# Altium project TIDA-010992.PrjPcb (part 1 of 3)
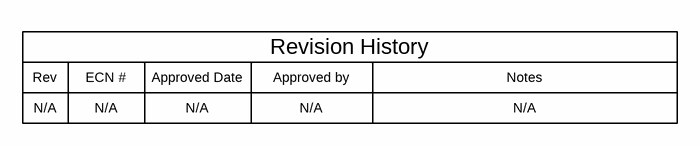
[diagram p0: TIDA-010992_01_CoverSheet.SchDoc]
CopyrightYear: 2025; DrawnBy: Chen Gao; PCB_Layout: Chen Gao; PCB_Rev: E1; PRJ_Customer: Public Release; PRJ_Engineer: Chen Gao; PRJ_Number: TIDA-010992; PRJ_Title: TIDA-010992; SCH_Rev: E1; TechSupport: http://www.ti.com/support; TID: TIDA-010992
13 sheets, 522 parts. Net scope: global (net labels, ports and power ports of the same name join across sheets).
Board file: TIDA-010992.PcbDoc
Sheets:
  TIDA-010992_01_CoverSheet.SchDoc
  TIDA-010992_02_Power.SchDoc
  TIDA-010992_03_IO_Map_Debug.SchDoc
  TIDA-010992_04_BOOT_SoC power_CLK.SchDoc
  TIDA-010992_05_ETH_Conn.SchDoc
  TIDA-010992_06_DRV_AXIS1.SchDoc
  TIDA-010992_07_DRV_AXIS2.SchDoc
  TIDA-010992_08_DRV_AXIS3.SchDoc
  TIDA-010992_09_DRV_AXIS4.SchDoc
  TIDA-010992_10_DRV_AXIS5.SchDoc
  TIDA-010992_11_DRV_AXIS6.SchDoc
  TIDA-010992_12_Connectors.SchDoc
  TIDA-010992_Hardware.SchDoc

## Sheet TIDA-010992_01_CoverSheet.SchDoc
size 431 x 279 mm; Date: Not shown in title block; ApprovedBy: Not shown in title block; CheckedBy: Not shown in title block; Author: Not shown in title block; CompanyName: Not shown in title block; Engineer: Not shown in title block; Organization: Not shown in title block; Address1: Not shown in title block; Address2: Not shown in title block; Address3: Not shown in title block; Address4: Not shown in title block; DocumentNumber: 1; Revision: Use project parameter SCH_Rev; SheetNumber: 1; SheetTotal: 13; PageSetup: Record=PageOptions¦CenterHorizontal=True¦CenterVertical=True¦PrintScale=1.00¦XCorrection=1.00¦YCorrection=1.00¦PrintKind=0¦BorderSize=5000000¦LeftOffset=0¦BottomOffset=0¦Orientation=2¦PaperLength=1000¦PaperWidth=1000¦Scale=100¦PaperSource=15¦PrintQuality=600¦MediaType=1¦DitherType=10¦PaperKind=Letter¦PrintScaleMode=1

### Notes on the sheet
- Rev
- N/A
- ECN #
- Approved Date
- Approved by
- Revision History
- Notes

## Sheet TIDA-010992_02_Power.SchDoc
size 431 x 279 mm; Date: Not shown in title block; ApprovedBy: Not shown in title block; CheckedBy: Not shown in title block; Author: Not shown in title block; CompanyName: Not shown in title block; Engineer: Not shown in title block; Organization: Not shown in title block; Address1: Not shown in title block; Address2: Not shown in title block; Address3: Not shown in title block; Address4: Not shown in title block; DocumentNumber: 2; Revision: Use project parameter SCH_Rev; SheetNumber: 2; SheetTotal: 13; PageSetup: Record=PageOptions¦CenterHorizontal=True¦CenterVertical=True¦PrintScale=1.00¦XCorrection=1.00¦YCorrection=1.00¦PrintKind=0¦BorderSize=5000000¦LeftOffset=0¦BottomOffset=0¦Orientation=2¦PaperLength=1000¦PaperWidth=1000¦Scale=100¦PaperSource=15¦PrintQuality=600¦MediaType=1¦DitherType=10¦PaperKind=Letter¦PrintScaleMode=1
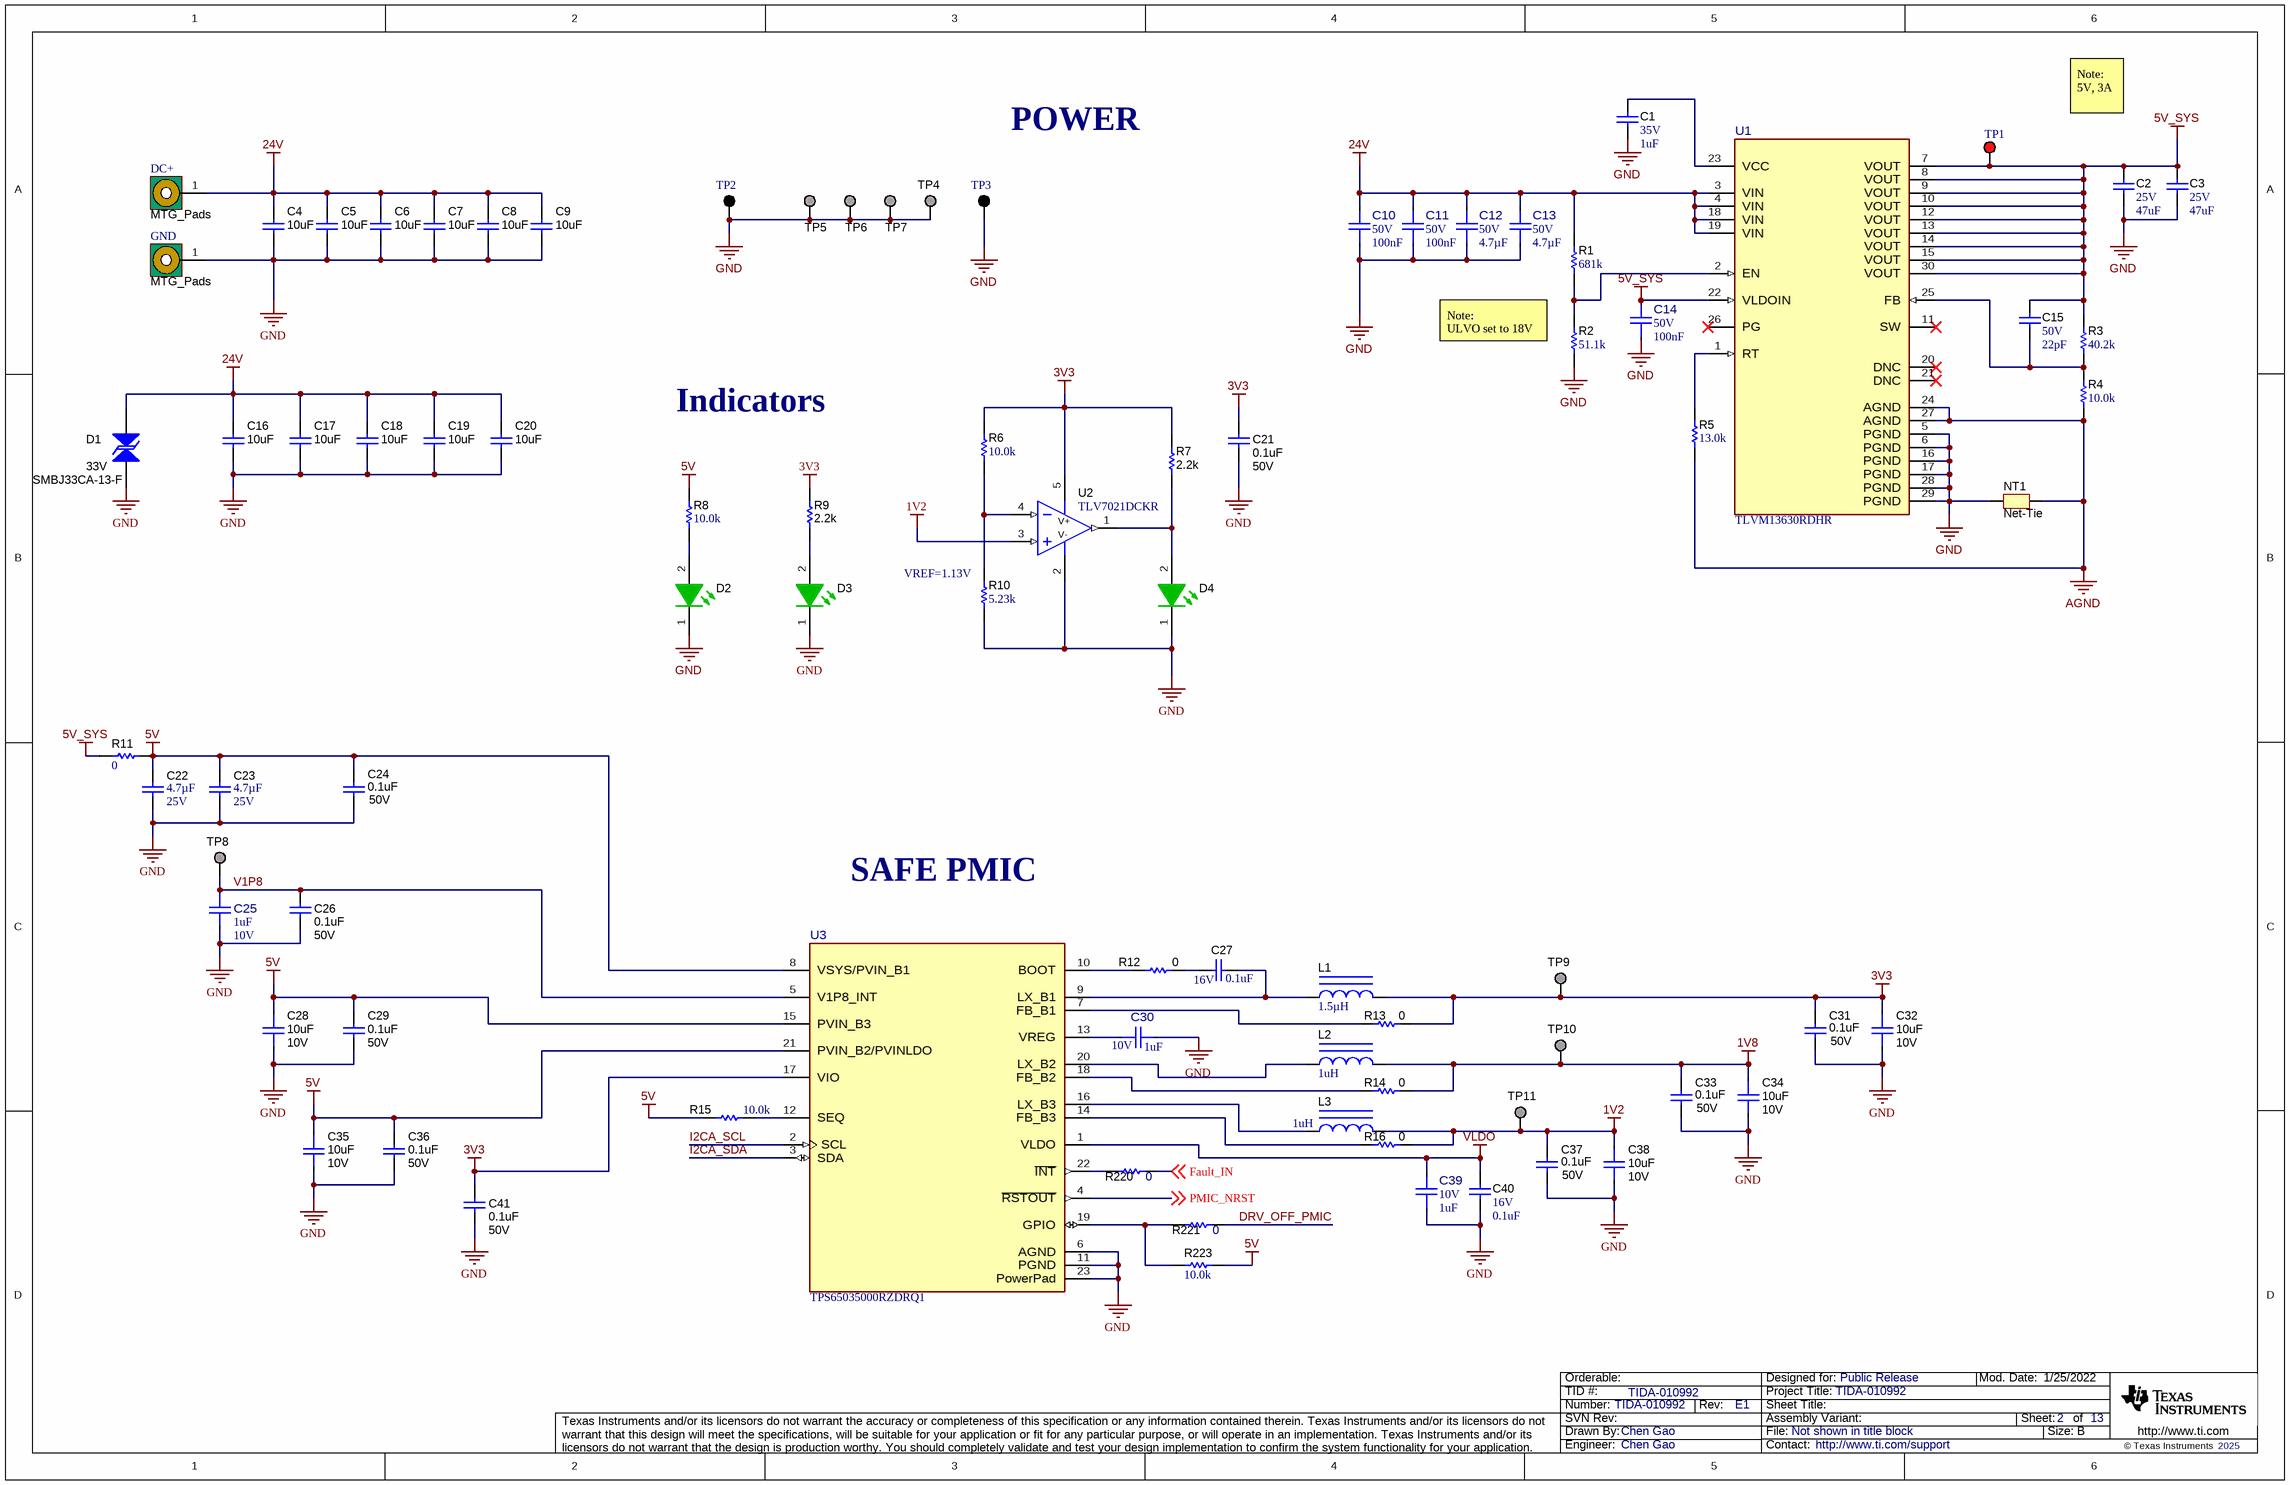
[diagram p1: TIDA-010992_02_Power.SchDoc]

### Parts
C1  VDC_V: 35V  ValueDisplayed: 1uF  [0402L]  (hidden comment: GRM155R6YA105ME11D)
C2  VDC_V: 25V  ValueDisplayed: 47uF  [1206_190]  (hidden comment: C3216X5R1E476M160AC)
C3  VDC_V: 25V  ValueDisplayed: 47uF  [1206_190]  (hidden comment: C3216X5R1E476M160AC)
C4  ValueDisplayed: 10uF  [1210_270L]  (hidden comment: GRM32ER71H106KA12L)
C5  ValueDisplayed: 10uF  [1210_270L]  (hidden comment: GRM32ER71H106KA12L)
C6  ValueDisplayed: 10uF  [1210_270L]  (hidden comment: GRM32ER71H106KA12L)
C7  ValueDisplayed: 10uF  [1210_270L]  (hidden comment: GRM32ER71H106KA12L)
C8  ValueDisplayed: 10uF  [1210_270L]  (hidden comment: GRM32ER71H106KA12L)
C9  ValueDisplayed: 10uF  [1210_270L]  (hidden comment: GRM32ER71H106KA12L)
C10  VDC_V: 50V  ValueDisplayed: 100nF  [FP-885012205086_0402-MFG]  (hidden comment: 885012205086)
C11  VDC_V: 50V  ValueDisplayed: 100nF  [FP-885012205086_0402-MFG]  (hidden comment: 885012205086)
C12  VDC_V: 50V  Cap_F: 4.7µF  [FP-C2012X7R1H475K125AC_0805-MFG]  (hidden comment: C2012X7R1H475K125AC)
C13  VDC_V: 50V  Cap_F: 4.7µF  [FP-C2012X7R1H475K125AC_0805-MFG]  (hidden comment: C2012X7R1H475K125AC)
C14  VDC_V: 50V  ValueDisplayed: 100nF  [FP-885012205086_0402-MFG]  (hidden comment: 885012205086)
C15  VDC_V: 50V  ValueDisplayed: 22pF  [0402L]  (hidden comment: CGA2B2C0G1H220J050BA)
C16  ValueDisplayed: 10uF  [1210_270L]  (hidden comment: GRM32ER71H106KA12L)
C17  ValueDisplayed: 10uF  [1210_270L]  (hidden comment: GRM32ER71H106KA12L)
C18  ValueDisplayed: 10uF  [1210_270L]  (hidden comment: GRM32ER71H106KA12L)
C19  ValueDisplayed: 10uF  [1210_270L]  (hidden comment: GRM32ER71H106KA12L)
C20  ValueDisplayed: 10uF  [1210_270L]  (hidden comment: GRM32ER71H106KA12L)
C21  VDC_V: 50V  ValueDisplayed: 0.1uF  [0402]  (hidden comment: CGA2B3X7R1H104M050BB)
C22  VDC_V: 25V  ValueDisplayed: 4.7µF  [0805L]  (hidden comment: CGA4J1X7R1E475K125AC)
C23  VDC_V: 25V  ValueDisplayed: 4.7µF  [0805L]  (hidden comment: CGA4J1X7R1E475K125AC)
C24  VDC_V: 50V  ValueDisplayed: 0.1uF  [0402]  (hidden comment: CGA2B3X7R1H104M050BB)
C25  VDC_V: 10V  ValueDisplayed: 1uF  [FP-GRM155C71A105KE11D_0402-MFG]  (hidden comment: GRM155C71A105KE11D)
C26  VDC_V: 50V  ValueDisplayed: 0.1uF  [0402]  (hidden comment: CGA2B3X7R1H104M050BB)
C27  VDC_V: 16V  ValueDisplayed: 0.1uF  [0201]  (hidden comment: GRM033Z71C104KE14D)
C28  VDC_V: 10V  ValueDisplayed: 10uF  [FP-CGA4J3X7S1A106K125AE_0805-MFG]  (hidden comment: CGA4J3X7S1A106K125AE)
C29  VDC_V: 50V  ValueDisplayed: 0.1uF  [0402]  (hidden comment: CGA2B3X7R1H104M050BB)
C30  VDC_V: 10V  ValueDisplayed: 1uF  [FP-GRM155C71A105KE11D_0402-MFG]  (hidden comment: GRM155C71A105KE11D)
C31  VDC_V: 50V  ValueDisplayed: 0.1uF  [0402]  (hidden comment: CGA2B3X7R1H104M050BB)
C32  VDC_V: 10V  ValueDisplayed: 10uF  [FP-CGA4J3X7S1A106K125AE_0805-MFG]  (hidden comment: CGA4J3X7S1A106K125AE)
C33  VDC_V: 50V  ValueDisplayed: 0.1uF  [0402]  (hidden comment: CGA2B3X7R1H104M050BB)
C34  VDC_V: 10V  ValueDisplayed: 10uF  [FP-CGA4J3X7S1A106K125AE_0805-MFG]  (hidden comment: CGA4J3X7S1A106K125AE)
C35  VDC_V: 10V  ValueDisplayed: 10uF  [FP-CGA4J3X7S1A106K125AE_0805-MFG]  (hidden comment: CGA4J3X7S1A106K125AE)
C36  VDC_V: 50V  ValueDisplayed: 0.1uF  [0402]  (hidden comment: CGA2B3X7R1H104M050BB)
C37  VDC_V: 50V  ValueDisplayed: 0.1uF  [0402]  (hidden comment: CGA2B3X7R1H104M050BB)
C38  VDC_V: 10V  ValueDisplayed: 10uF  [FP-CGA4J3X7S1A106K125AE_0805-MFG]  (hidden comment: CGA4J3X7S1A106K125AE)
C39  VDC_V: 10V  ValueDisplayed: 1uF  [FP-GRM155C71A105KE11D_0402-MFG]  (hidden comment: GRM155C71A105KE11D)
C40  VDC_V: 16V  ValueDisplayed: 0.1uF  [0201]  (hidden comment: GRM033Z71C104KE14D)
C41  VDC_V: 50V  ValueDisplayed: 0.1uF  [0402]  (hidden comment: CGA2B3X7R1H104M050BB)
D1  SMBJ33CA-13-F  value 33V  [SMB-Bi]
D2  150040GS73240  [WL-SMCC_0402_Green]  (value not drawn)
D3  150040GS73240  [WL-SMCC_0402_Green]  (value not drawn)
D4  150040GS73240  [WL-SMCC_0402_Green]  (value not drawn)
DC+  MTG_Pads  [MTGP_2-48_PanHead]  (no BOM)
GND  MTG_Pads  [MTGP_2-48_PanHead]  (no BOM)
L1  ValueDisplayed: 1.5µH  [TFM201610ALMA]  (hidden comment: TFM201610ALMA1R5MTAA)
L2  ValueDisplayed: 1uH  [TFM201610]  (hidden comment: TFM201610GHM-1R0MTAA)
L3  ValueDisplayed: 1uH  [TFM201610]  (hidden comment: TFM201610GHM-1R0MTAA)
NT1  Net-Tie  [Net-Tie7milsWide_20milsLong]  (net tie, no BOM)
R1  ValueDisplayed: 681k  [0402L]  (hidden comment: CRCW0402681KFKED)
R2  ValueDisplayed: 51.1k  [0402L]  (hidden comment: CRCW040251K1FKED)
R3  ValueDisplayed: 40.2k  [0402L]  (hidden comment: CRCW040240K2FKED)
R4  ValueDisplayed: 10.0k  [0402L]  (hidden comment: CRCW040210K0FKED)
R5  ValueDisplayed: 13.0k  [0402L]  (hidden comment: CRCW040213K0FKED)
R6  ValueDisplayed: 10.0k  [0402L]  (hidden comment: CRCW040210K0FKED)
R7  ValueDisplayed: 2.2k  [0402]  (hidden comment: CRCW04022K20JNED)
R8  ValueDisplayed: 10.0k  [0402L]  (hidden comment: CRCW040210K0FKED)
R9  ValueDisplayed: 2.2k  [0402]  (hidden comment: CRCW04022K20JNED)
R10  ValueDisplayed: 5.23k  [0402]  (hidden comment: CRCW04025K23FKED)
R11  ValueDisplayed: 0  [0603]  (hidden comment: PMR03EZPJ000)
R12  Res_ohm: 0  [FP-RC0201JR-070RL_0201 (0603 Metric)-IPC_C]  (hidden comment: RC0201JR-070RL)
R13  Res_ohm: 0  [FP-RC0201JR-070RL_0201 (0603 Metric)-IPC_C]  (hidden comment: RC0201JR-070RL)
R14  Res_ohm: 0  [FP-RC0201JR-070RL_0201 (0603 Metric)-IPC_C]  (hidden comment: RC0201JR-070RL)
R15  ValueDisplayed: 10.0k  [0402L]  (hidden comment: CRCW040210K0FKED)
R16  Res_ohm: 0  [FP-RC0201JR-070RL_0201 (0603 Metric)-IPC_C]  (hidden comment: RC0201JR-070RL)
R220  ValueDisplayed: 0  [0402]  (hidden comment: CRCW04020000Z0EDHP)
R221  ValueDisplayed: 0  [0402]  (hidden comment: CRCW04020000Z0EDHP)
R223  ValueDisplayed: 10.0k  [0402L]  (hidden comment: CRCW040210K0FKED)
TP1  5000  [Keystone5000]  (value not drawn)
TP2  CMP-0055138-2  [Keystone5001]  (value not drawn)
TP3  CMP-0055138-2  [Keystone5001]  (value not drawn)
TP4  TP_SM_1MM  [TP_SM_1MM]  (value not drawn)  (no BOM)
TP5  TP_SM_1MM  [TP_SM_1MM]  (value not drawn)  (no BOM)
TP6  TP_SM_1MM  [TP_SM_1MM]  (value not drawn)  (no BOM)
TP7  TP_SM_1MM  [TP_SM_1MM]  (value not drawn)  (no BOM)
TP8  TESTPOINT  [TP_25MIL-SMT]  (value not drawn)  (no BOM)
TP9  TESTPOINT  [TP_25MIL-SMT]  (value not drawn)  (no BOM)
TP10  TESTPOINT  [TP_25MIL-SMT]  (value not drawn)  (no BOM)
TP11  TESTPOINT  [TP_25MIL-SMT]  (value not drawn)  (no BOM)
U1  TLVM13630RDHR  [RDH0030A-MFG]
U2  TLV7021DCKR  [DCK0005A_N]
U3  TPS65035000RZDRQ1  [RZD0022A-MFG]

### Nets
1V2: C37.1 C38.1 L3.2 R16.2 TP11.1 U2.3(IN+)
1V8: C33.1 C34.1 L2.2 R14.2 TP10.1
3V3: C21.1 C31.1 C32.1 C41.1 L1.2 R6.1 R7.2 R9.2 R13.2 TP9.1 U2.5(V+) U3.17(VIO)
5V: C22.1 C23.1 C24.1 C28.1 C29.1 C35.1 C36.1 R8.1 R11.1 R15.2 R223.2 U3.8(VSYS/PVIN_B1) U3.15(PVIN_B3) U3.21(PVIN_B2/PVINLDO)
5V_SYS: C2.1 C3.1 C14.2 C15.1 R3.2 R11.2 TP1.1 U1.7(VOUT) U1.8(VOUT) U1.9(VOUT) U1.10(VOUT) U1.12(VOUT) U1.13(VOUT) U1.14(VOUT) U1.15(VOUT) U1.22(VLDOIN) U1.30(VOUT)
24V: C4.2 C5.2 C6.2 C7.2 C8.2 C9.2 C10.2 C11.2 C12.2 C13.2 C16.2 C17.2 C18.2 C19.2 C20.2 D1.2 DC+.1 R1.2 U1.3(VIN) U1.4(VIN) U1.18(VIN) U1.19(VIN)
AGND: NT1.2 R4.1 R5.1 U1.24(AGND) U1.27(AGND)
GND: C1.2 C2.2 C3.2 C4.1 C5.1 C6.1 C7.1 C8.1 C9.1 C10.1 C11.1 C12.1 C13.1 C14.1 C16.1 C17.1 C18.1 C19.1 C20.1 C21.2 C22.2 C23.2 C24.2 C25.2 C26.2 C28.2 C29.2 C30.2 C31.2 C32.2 C33.2 C34.2 C35.2 C36.2 C37.2 C38.2 C39.1 C40.1 C41.2 D1.1 D2.1(K) D3.1(K) D4.1(K) GND.1 NT1.1 R2.1 R10.1 TP2.1 TP3.1 TP4.1 TP5.1 TP6.1 TP7.1 U1.5(PGND) U1.6(PGND) U1.16(PGND) U1.17(PGND) U1.28(PGND) U1.29(PGND) U2.2(V-) U3.6(AGND) U3.11(PGND) U3.23(PowerPad)
VLDO: C39.2 C40.2 U3.1(VLDO)
DRV_OFF_PMIC: R221.2
Fault_IN: R220.2 ; off-sheet Fault_IN
I2CA_SCL: U3.2(SCL)
I2CA_SDA: U3.3(SDA)
PMIC_NRST: U3.4(~{RSTOUT}) ; off-sheet PMIC_NRST
V1P8: C25.1 C26.1 TP8.1 U3.5(V1P8_INT)
NetC1_1: C1.1 U1.23(VCC)
NetC15_2: C15.2 R3.1 R4.2 U1.25(FB)
NetC27_1: C27.1 R12.2
NetC27_2: C27.2 L1.1 U3.9(LX_B1)
NetC30_1: C30.1 U3.13(VREG)
NetD2_2: D2.2(A) R8.2
NetD3_2: D3.2(A) R9.1
NetD4_2: D4.2(A) R7.1 U2.1(OUT)
NetL2_1: L2.1 U3.20(LX_B2)
NetL3_1: L3.1 U3.16(LX_B3)
NetR1_1: R1.1 R2.2 U1.2(EN)
NetR5_2: R5.2 U1.1(RT)
NetR6_2: R6.2 R10.2 U2.4(IN-)
NetR12_1: R12.1 U3.10(BOOT)
NetR13_1: R13.1 U3.7(FB_B1)
NetR14_1: R14.1 U3.18(FB_B2)
NetR15_1: R15.1 U3.12(SEQ)
NetR16_1: R16.1 U3.14(FB_B3)
NetR220_1: R220.1 U3.22(~{INT})
NetR221_1: R221.1 R223.1 U3.19(GPIO)

Not connected (* = marked no-connect by the designer): U1 11(SW)* 20(DNC)* 21(DNC)* 26(PG)*

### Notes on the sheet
- POWER
- Note:
  5V, 3A
- Note:
  ULVO set to 18V
- Indicators
- (near R10) VREF=1.13V
- SAFE PMIC

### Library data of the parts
C1 = CMP-0006620-2: CAP, CERM, 1 uF, 35 V, +/- 20%, X5R, 0402; Manufacturer: MuRata; TaMin_C: -55°C; Polarized: N; SizeAreaWB_mm2: 3; Value1: Unknown; U/M: EA; Value: 1uF; TaMax_C: 85°C; SizeZ_mm: 0.6; SizeX_mm: 1; SizeY_mm: 0.5; Cap_Case: 0402; Cap_F: 1µF; AEC Category: Q200
C2 C3 = CMP-0008656-2: CAP, CERM, 47 uF, 25 V, +/- 20%, X5R, 1206_190; Manufacturer: TDK; TaMin_C: -55°C; Polarized: N; SizeAreaWB_mm2: 10.92; Value1: Unknown; U/M: EA; Value: 47uF; TaMax_C: 85°C; SizeZ_mm: 1.9; SizeX_mm: 3.2; SizeY_mm: 1.6; Cap_Case: 1206; SizeArea_mm2: 5.12; Cap_F: 47µF; AEC Category: Q200
C4-C9 C16-C20 = CMP-0009226-3: CAP, CERM, 10 uF, 50 V, +/- 10%, X7R, 1210; Manufacturer: MuRata; TaMin_C: -55°C; Polarized: N; SizeAreaWB_mm2: 14.7; Value1: Unknown; U/M: EA; Value: 10uF; TaMax_C: 125°C; SizeZ_mm: 2.7; SizeX_mm: 3.2; SizeY_mm: 2.5; Cap_Case: 1210; Value2: 50V; SizeArea_mm2: 8; Cap_F: 10µF; AEC Category: Q200
C10 C11 C14 = CMP-0096737-1: 100 nF ±10% 50V Ceramic Capacitor X7R 0402 (1005 Metric); Manufacturer: Wurth; SizeZ_mm: 0.7mm; TempCo: 15%; AEC Qualified: No; Value: 100nF
C12 C13 = CMP-0088943-1: 4.7µF ±10% 50V Ceramic Capacitor X7R 0805 (2012 Metric); Manufacturer: TDK; TempCo: 15%; AEC Qualified: No; ValueDisplayed: 4.7uF; SizeZ_mm: 1.5mm
C15 = CMP-0860831-1: CAP, CERM, 22 pF, 50 V,+/- 5%, C0G/NP0, AEC-Q200 Grade 1, 0402; Manufacturer: TDK; Cap_Case: 0402; AEC Grade: 1; AEC Category: Q200; TaMin_C: -55°C; SizeY_mm: 0.5; Polarized: N; U/M: EA; SizeZ_mm: 0.6; AEC Qualified: Y; SizeAreaWB_mm2: 3; TaMax_C: 125°C; Value: 22pF
C21 C24 C26 C29 C31 C33 C36 C37 C41 = CMP-0006326-2: CAP, CERM, 0.1 uF, 50 V, +/- 20%, X7R, AEC-Q200 Grade 1, 0402; Manufacturer: TDK; TaMin_C: -55°C; Polarized: N; SizeAreaWB_mm2: 3; Value1: Unknown; U/M: EA; Value: 0.1uF; TaMax_C: 125°C; SizeZ_mm: 0.6; SizeX_mm: 1; SizeY_mm: 0.5; AEC Qualified: Y; Cap_F: 100nF; AEC Category: Q200
C22 C23 = CMP-0076706-1: CAP, CERM, 4.7 µF, 25 V,+/- 10%, X7R, AEC-Q200 Grade 1, 0805; Manufacturer: TDK; TaMin_C: -55°C; Polarized: N; SizeAreaWB_mm2: 6.75; U/M: EA; Value: 4.7uF; TaMax_C: 125°C; SizeZ_mm: 1.45; SizeX_mm: 2.0; SizeY_mm: 1.25; Cap_Case: 2x1.25x1.25mm; SizeArea_mm2: 2.5; AEC Qualified: Y; AEC Grade: 1; AEC Category: Q200
C25 C30 C39 = CMP-0035346-1: 1µF ±10% 10V Ceramic Capacitor X7S 0402 (1005 Metric); Manufacturer: Murata; TempCo: 22%; SizeZ_mm: 0.6mm; AEC Qualified: No
C27 C40 = CMP-0064970-1: CAP, CERM, 0.1 uF, 16 V,+/- 10%, X7R, 0201; Manufacturer: MuRata; TaMin_C: -55°C; Polarized: N; SizeAreaWB_mm2: 2.08; Value1: Unknown; U/M: EA; Value: 0.1uF; TaMax_C: 125°C; SizeZ_mm: 0.26; SizeX_mm: 0.6; SizeY_mm: 0.3; SizeArea_mm2: 0.18; Cap_F: 100nF; AEC Category: Q200
C28 C32 C34 C35 C38 = CMP-0089543-1: 10µF ±10% 10V Ceramic Capacitor X7S 0805 (2012 Metric); Manufacturer: TDK; SizeZ_mm: 1.5mm; AEC Grade: Grade 1; AEC Qualified: Yes; TempCo: 22%
D1 = CMP-0005564-3: Diode, TVS, Bi, 33 V, SMB; Manufacturer: Diodes Inc.; SizeX_mm: 5.6; Ppk: 600W; SizeAreaWB_mm2: 44.156; SizeZ_mm: 2.6; SizeArea_mm2: 21.336; SizeY_mm: 3.81; AEC Category: Q101
D2-D4 = CMP-0081765-2: LED, Green, SMD; Manufacturer: Wurth Elektronik; Vr_V: 5V; Io_A: 20mA; Tjmax_C: 95°C; Ir_A: 10µA; Power_TotalModule: 99mW; Value2: 3.2V; SizeArea_mm2: 0.5; SizeX_mm: 1; Value1: 0.099W; Angle: 120; Type: InGaN; SizeAreaWB_mm2: 3
DC+ GND = CMP-0078421-2: PCB Mounting Hole; Manufacturer: Any; Key: Mounting Hole (Imperial) with Pads
L1 = CMP-0081093-1: Inductor, Shielded, Metal Composite, 1.5 µH, 2.3 A, 0.11 ohm, AEC-Q200 Grade 0, SMD; Manufacturer: TDK; Isat: 2.8A @ 30% inductance drop; Irms: 2.3A @ 40C rise; SizeAreaWB_mm2: 7.8; DCR_ohm: 0.11; Value: 1.5uH; Imax_A: 2.3A; SizeZ_mm: 1; SizeX_mm: 2; SizeY_mm: 1.6; SizeArea_mm2: 3.2; AEC Qualified: Y; AEC Grade: 0; AEC Category: Q200
L2 L3 = CMP-0062877-1: Inductor, 1 uH, 3.1 A, 0.06 ohm, SMD; Manufacturer: TDK; Isat: 3.6A @ 30% inductance drop; Irms: 3.1A @ 40C rise; Green_Lifecycle: Active; SizeAreaWB_mm2: 7.8; DCR_ohm: 60m; Green_REACh: Passed; Value: 1uH; Imax_A: 3.1A; SizeZ_mm: 1; SizeX_mm: 2; SizeY_mm: 1.6; SizeArea_mm2: 3.2; Ind_H: 1µH; AEC Qualified: N; AEC Category: Q200
NT1 = CMP-0078142-5: Single point connection between nets.
R1 = CMP-0026504-2: RES, 681 k, 1%, 0.063 W, AEC-Q200 Grade 0, 0402; Manufacturer: Vishay-Dale; Power_W: 63mW; TempCo: 100 ppm/C; Value: 681k; EIA_Code: E96; SizeX_mm: 1; SizeY_mm: 0.5; SizeZ_mm: 0.6; Value2: 0.063W; AEC Qualified: Y; VDC_V: 50V; AEC Category: Q200; AEC Grade: 0
R2 = CMP-0026437-2: RES, 51.1 k, 1%, 0.063 W, AEC-Q200 Grade 0, 0402; Manufacturer: Vishay-Dale; Power_W: 63mW; TempCo: 100 ppm/C; Value_Code: 51k1; Value: 51.1k; EIA_Code: E96; SizeX_mm: 1; SizeY_mm: 0.5; SizeZ_mm: 0.6; Value2: 0.063W; AEC Qualified: Y; VDC_V: 50V; AEC Category: Q200; AEC Grade: 0
R3 = CMP-0026367-2: RES, 40.2 k, 1%, 0.063 W, AEC-Q200 Grade 0, 0402; Manufacturer: Vishay-Dale; Power_W: 63mW; TempCo: 100 ppm/C; Value_Code: 40k2; Value: 40.2k; EIA_Code: E96; SizeX_mm: 1; SizeY_mm: 0.5; SizeZ_mm: 0.6; Value2: 0.063W; AEC Qualified: Y; VDC_V: 50V; AEC Category: Q200; AEC Grade: 0
R4 R6 R8 R15 R223 = CMP-0025958-3: RES, 10.0 k, 1%, 0.063 W, AEC-Q200 Grade 0, 0402; Manufacturer: Vishay-Dale; Power_W: 63mW; TempCo: 100 ppm/C; Value_Code: 10k0; Value: 10.0k; EIA_Code: E96; Res_ohm: 10k; SizeX_mm: 1; SizeY_mm: 0.5; SizeZ_mm: 0.6; Value2: 0.063W; AEC Qualified: Y; VDC_V: 50V; AEC Category: Q200; AEC Grade: 0
R5 = CMP-0026003-3: RES, 13.0 k, 1%, 0.063 W, AEC-Q200 Grade 0, 0402; Manufacturer: Vishay-Dale; Power_W: 63mW; TempCo: 100 ppm/C; Value_Code: 13k0; Value: 13.0k; EIA_Code: E96; Res_ohm: 13k; SizeX_mm: 1; SizeY_mm: 0.5; SizeZ_mm: 0.6; Value2: 0.063W; AEC Qualified: Y; VDC_V: 50V; AEC Category: Q200; AEC Grade: 0
R7 R9 = CMP-0026890-5: RES, 2.2 k, 5%, 0.063 W, AEC-Q200 Grade 0, 0402; Manufacturer: Vishay-Dale; Value: 2.2k; Value_Code: 2k20; Power_W: 63mW; Value2: 0.063W; VDC_V: 50V; TempCo: 200 ppm/C; SizeArea_mm2: 0.5; SizeX_mm: 1; SizeZ_mm: 0.6; EIA_Code: E24; AEC Category: Q200; AEC Qualified: Y; AEC Grade: 0
R10 = CMP-0026464-2: RES, 5.23 k, 1%, 0.063 W, AEC-Q200 Grade 0, 0402; Manufacturer: Vishay-Dale; Power_W: 63mW; TempCo: 100 ppm/C; Value_Code: 5k23; Value: 5.23k; EIA_Code: E96; SizeX_mm: 1; SizeY_mm: 0.5; SizeZ_mm: 0.6; Value2: 0.063W; AEC Qualified: Y; VDC_V: 50V; AEC Category: Q200; AEC Grade: 0
R11 = CMP-0086358-1: RES, 0, 0%, 0.25 W, AEC-Q200 Grade 0, 0603; Manufacturer: Rohm; Power_W: 250mW; SizeZ_mm: 1; SizeArea_mm2: 1.28; Value2: 0.25W; SizeAreaWB_mm2: 4.68; Value_Code: 0000; Value: 0; AEC Qualified: Y; AEC Category: Q200; SizeX_mm: 1.6; SizeY_mm: 0.8
R12-R14 R16 = CMP-0086442-2: RES SMD 0 OHM JUMPER 1/20W 0201; Manufacturer: Yageo; Power_W: 50mW; VDC_V: 25V; AEC Qualified: No; Tolerance_%: 5%; TempCo: 200ppm/°C; SizeZ_mm: 0.26mm
R220 R221 = CMP-0081856-1: RES, 0, 0%, 0.2 W, AEC-Q200 Grade 0, 0402; Manufacturer: Vishay-Dale; SizeAreaWB_mm2: 3; SizeArea_mm2: 0.5; AEC Qualified: Y; AEC Category: Q200; Value: 0; SizeZ_mm: 0.6; Power_W: 200mW; VDC_V: 50V; Value2: 0.2W; SizeX_mm: 1
TP1 = CMP-0055137-2: Test Point, Miniature, Red, TH; Manufacturer: Keystone Electronics; Green_REACh: Passed; Green_Lifecycle: Active; ContactFinish: Silver; CNHeader: FALSE; CT: TRUE
TP2 TP3 = CMP-0055138-2: Test Point, Miniature, Black, TH; Manufacturer: Keystone Electronics; ContactFinish: Silver; CNHeader: FALSE; Green_Lifecycle: Active; Green_REACh: Passed; CT: TRUE
TP4-TP7 = CMP-0003825-1: 1mm Test Point, SMT; Manufacturer: Any
TP8-TP11 = CMP-0078143-3: TEST POINT.  No entry in BOM.
U1 = CMP-0092030-4: 3-V to 36-V Input, 1-V to 6-V Output, 3-A Power Module; Manufacturer: Texas Instruments; Max Supply Voltage: 36V; Standoff Height: 0mm; AEC Qualified: No; CompType: IC; Min Supply Voltage: 3V; Switching Topology: Buck; AEC Category: Q200; TaMin_C: -40°C; TaMax_C: +105°C; Output Voltage: 1-6V; Switching Frequency: 200-2200kHz; Output Type: AdjustableProgrammable; SizeZ_mm: 1.9mm; Number Of Outputs: 1
U2 = CMP-0085889-2: Small-Size Micropower Low-Voltage Comparator, DCK0005A (SOT-SC70-5); Manufacturer: Texas Instruments; Alternate PartNumber: TLV7021DCKT; SizeAreaWB_mm2: 9.3; SizeY_mm: 2; Rating: Catalog; SizeZ_mm: 1.1; SizeX_mm: 2.1; CompType: IC; AEC Qualified: N; SizeArea_mm2: 4.2; AEC Category: Q200
U3 = CMP-0097122-2: Automotive Camera PMIC; Manufacturer: Texas Instruments; Number Of Outputs: 4; Nominal Supply Current: 10mA; TaMax_C: +125°C; Min Supply Voltage: 2.5V; Output Voltage: 2.5-4/0.9-1.9/1.8-3.3V; Standoff Height: 0mm; TJmax_C: +150°C; SizeZ_mm: 1.05mm; AEC Grade: Grade 1; Max Supply Voltage: 18.3V; TaMin_C: -40°C; AEC Qualified: Yes; AEC Category: Q200; CompType: IC

## Sheet TIDA-010992_03_IO_Map_Debug.SchDoc
size 431 x 279 mm; Date: Not shown in title block; ApprovedBy: Not shown in title block; CheckedBy: Not shown in title block; Author: Not shown in title block; CompanyName: Not shown in title block; Engineer: Not shown in title block; Organization: Not shown in title block; Address1: Not shown in title block; Address2: Not shown in title block; Address3: Not shown in title block; Address4: Not shown in title block; DocumentNumber: 3; Revision: Use project parameter SCH_Rev; SheetNumber: 3; SheetTotal: 13; PageSetup: Record=PageOptions¦CenterHorizontal=True¦CenterVertical=True¦PrintScale=1.00¦XCorrection=1.00¦YCorrection=1.00¦PrintKind=0¦BorderSize=5000000¦LeftOffset=0¦BottomOffset=0¦Orientation=2¦PaperLength=1000¦PaperWidth=1000¦Scale=100¦PaperSource=15¦PrintQuality=600¦MediaType=1¦DitherType=10¦PaperKind=Letter¦PrintScaleMode=1
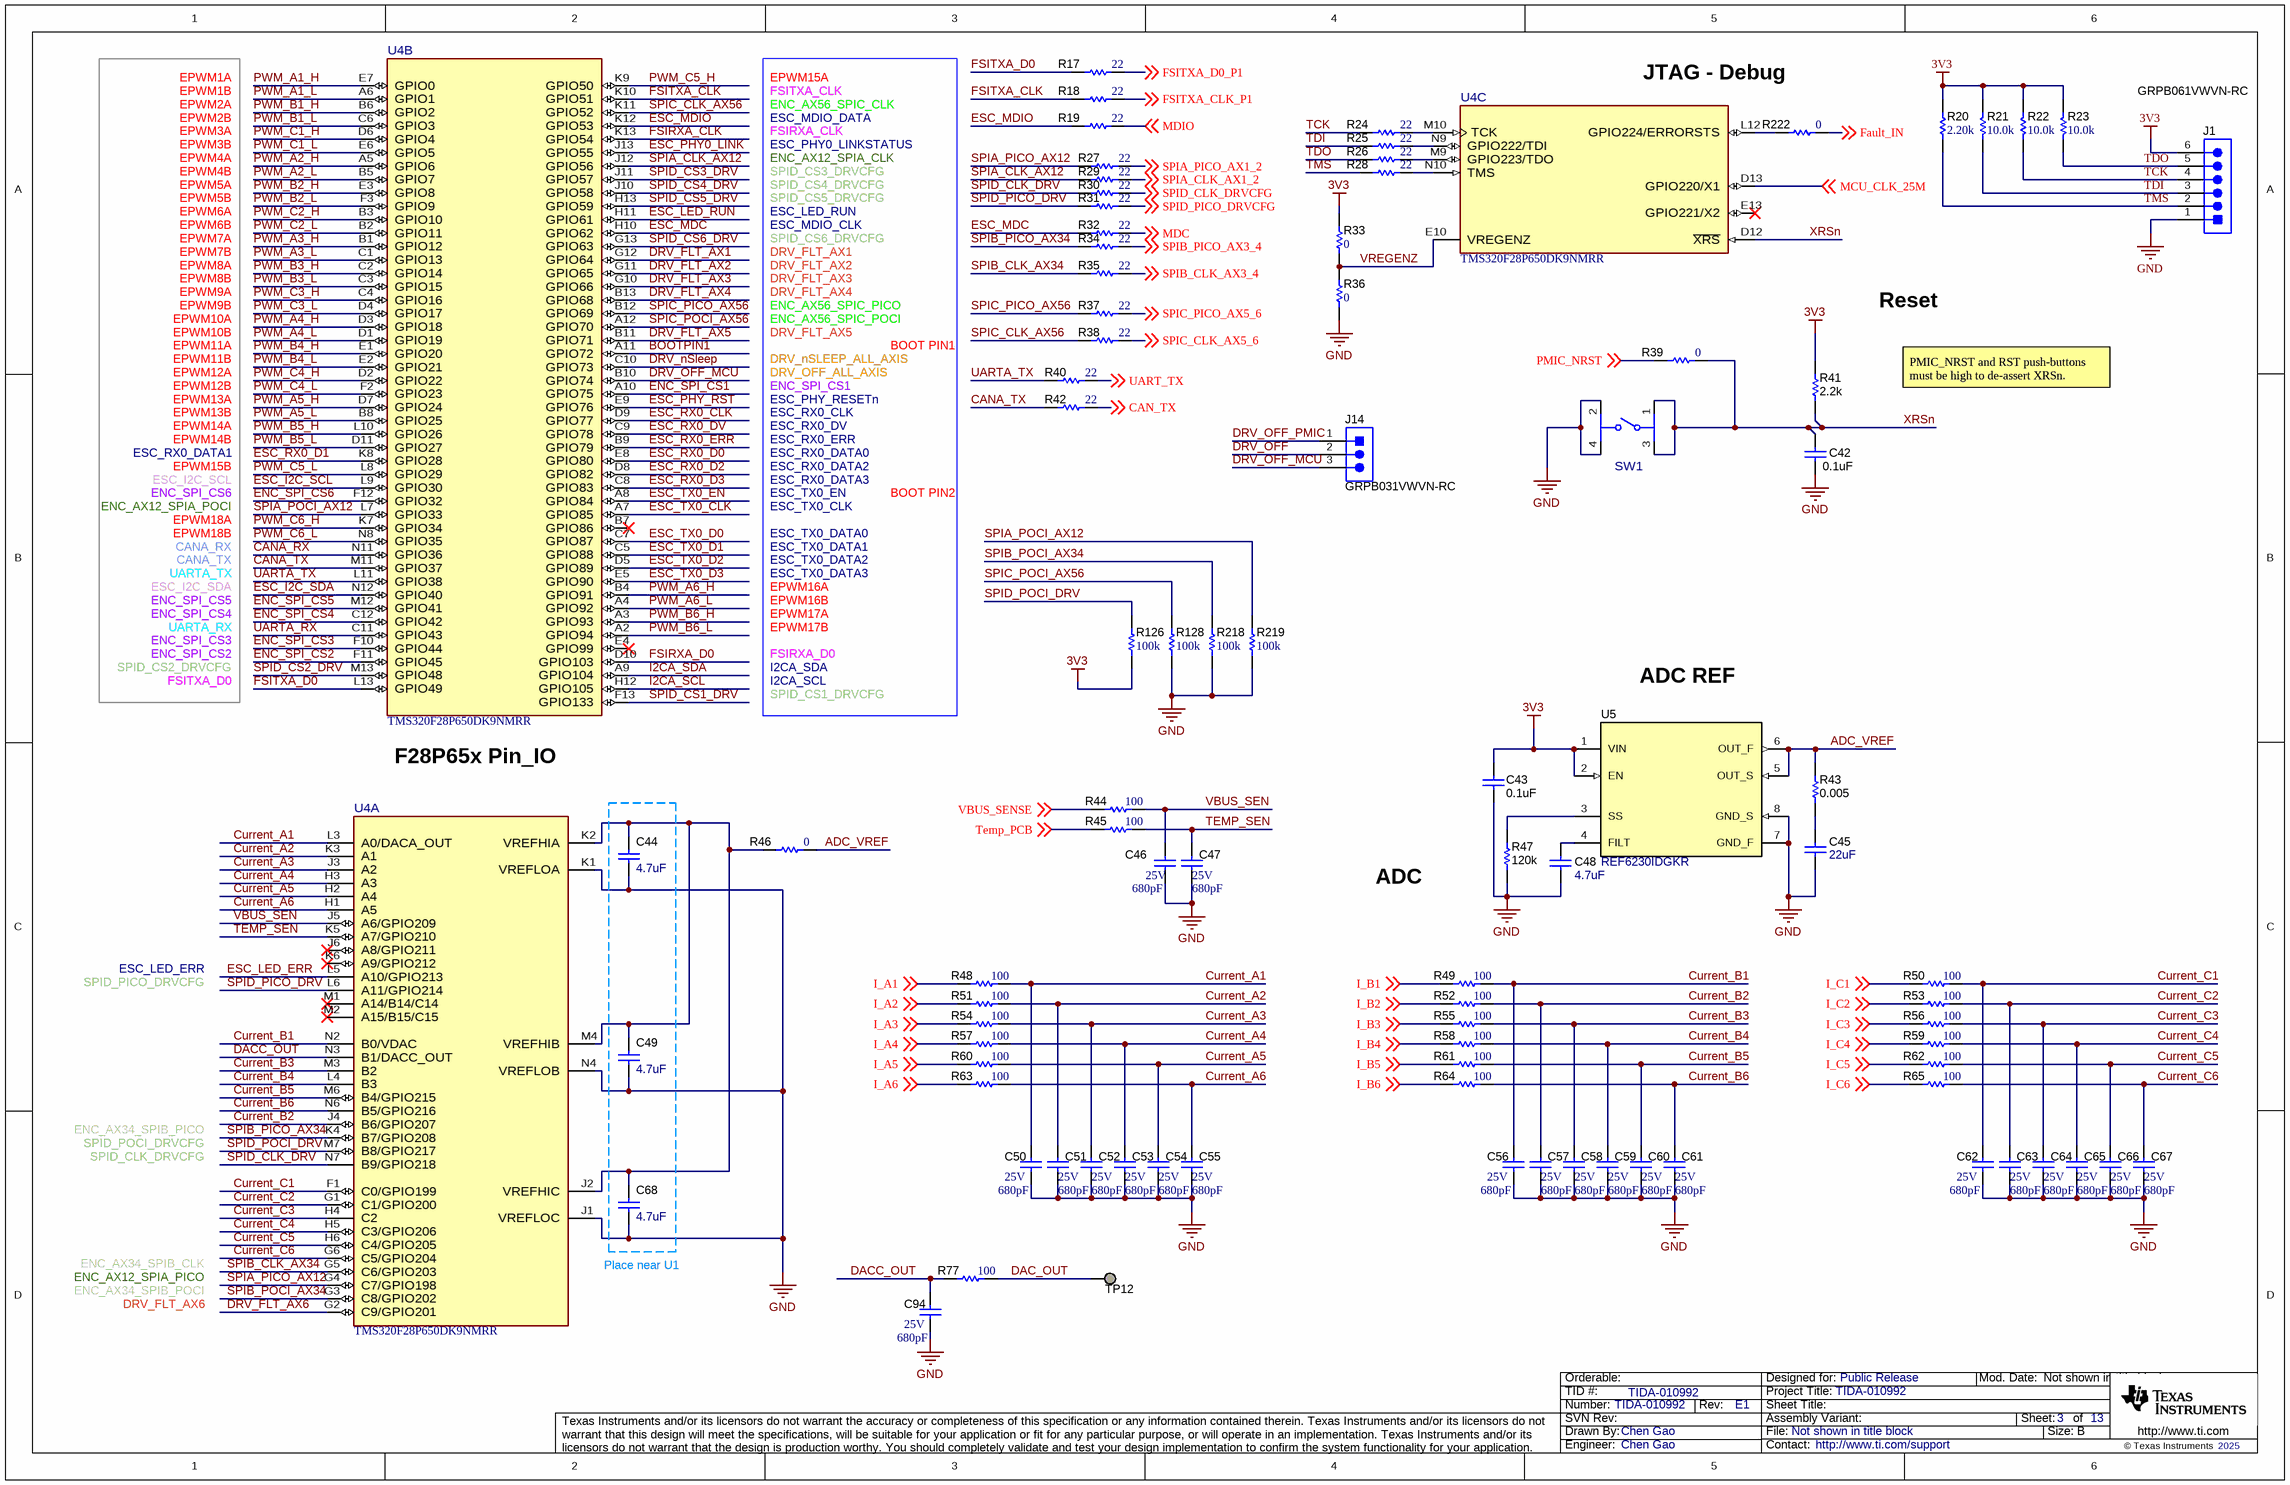
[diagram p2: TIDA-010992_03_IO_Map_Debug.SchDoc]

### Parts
C42  ValueDisplayed: 0.1uF  [0402]  (hidden comment: 885012205037)
C43  ValueDisplayed: 0.1uF  [0402]  (hidden comment: 885012205037)
C44  ValueDisplayed: 4.7uF  [0603]  (hidden comment: GRM188R61C475KAAJ)
C45  ValueDisplayed: 22uF  [0603]  (hidden comment: GRM188R61A226ME15D)
C46  VDC_V: 25V  ValueDisplayed: 680pF  [0201]  (hidden comment: GRM033R71E681KA01D)
C47  VDC_V: 25V  ValueDisplayed: 680pF  [0201]  (hidden comment: GRM033R71E681KA01D)
C48  ValueDisplayed: 4.7uF  [0603]  (hidden comment: GRM188R61C475KAAJ)
C49  ValueDisplayed: 4.7uF  [0603]  (hidden comment: GRM188R61C475KAAJ)
C50  VDC_V: 25V  ValueDisplayed: 680pF  [0201]  (hidden comment: GRM033R71E681KA01D)
C51  VDC_V: 25V  ValueDisplayed: 680pF  [0201]  (hidden comment: GRM033R71E681KA01D)
C52  VDC_V: 25V  ValueDisplayed: 680pF  [0201]  (hidden comment: GRM033R71E681KA01D)
C53  VDC_V: 25V  ValueDisplayed: 680pF  [0201]  (hidden comment: GRM033R71E681KA01D)
C54  VDC_V: 25V  ValueDisplayed: 680pF  [0201]  (hidden comment: GRM033R71E681KA01D)
C55  VDC_V: 25V  ValueDisplayed: 680pF  [0201]  (hidden comment: GRM033R71E681KA01D)
C56  VDC_V: 25V  ValueDisplayed: 680pF  [0201]  (hidden comment: GRM033R71E681KA01D)
C57  VDC_V: 25V  ValueDisplayed: 680pF  [0201]  (hidden comment: GRM033R71E681KA01D)
C58  VDC_V: 25V  ValueDisplayed: 680pF  [0201]  (hidden comment: GRM033R71E681KA01D)
C59  VDC_V: 25V  ValueDisplayed: 680pF  [0201]  (hidden comment: GRM033R71E681KA01D)
C60  VDC_V: 25V  ValueDisplayed: 680pF  [0201]  (hidden comment: GRM033R71E681KA01D)
C61  VDC_V: 25V  ValueDisplayed: 680pF  [0201]  (hidden comment: GRM033R71E681KA01D)
C62  VDC_V: 25V  ValueDisplayed: 680pF  [0201]  (hidden comment: GRM033R71E681KA01D)
C63  VDC_V: 25V  ValueDisplayed: 680pF  [0201]  (hidden comment: GRM033R71E681KA01D)
C64  VDC_V: 25V  ValueDisplayed: 680pF  [0201]  (hidden comment: GRM033R71E681KA01D)
C65  VDC_V: 25V  ValueDisplayed: 680pF  [0201]  (hidden comment: GRM033R71E681KA01D)
C66  VDC_V: 25V  ValueDisplayed: 680pF  [0201]  (hidden comment: GRM033R71E681KA01D)
C67  VDC_V: 25V  ValueDisplayed: 680pF  [0201]  (hidden comment: GRM033R71E681KA01D)
C68  ValueDisplayed: 4.7uF  [0603]  (hidden comment: GRM188R61C475KAAJ)
C94  VDC_V: 25V  ValueDisplayed: 680pF  [0201]  (hidden comment: GRM033R71E681KA01D)
J1  GRPB061VWVN-RC  [Sullins_GRPB061VWVN-RC]
J14  GRPB031VWVN-RC  [Sullins_GRPB031VWVN-RC]
R17  ValueDisplayed: 22  [0201]  (hidden comment: ERJ-1GNJ220C)
R18  ValueDisplayed: 22  [0201]  (hidden comment: ERJ-1GNJ220C)
R19  ValueDisplayed: 22  [0201]  (hidden comment: ERJ-1GNJ220C)
R20  ValueDisplayed: 2.20k  [0402]  (hidden comment: CRCW04022K20FKED)
R21  ValueDisplayed: 10.0k  [0402]  (hidden comment: ERJ-2RKF1002X)
R22  ValueDisplayed: 10.0k  [0402]  (hidden comment: ERJ-2RKF1002X)
R23  ValueDisplayed: 10.0k  [0402]  (hidden comment: ERJ-2RKF1002X)
R24  ValueDisplayed: 22  [0201]  (hidden comment: ERJ-1GNJ220C)
R25  ValueDisplayed: 22  [0201]  (hidden comment: ERJ-1GNJ220C)
R26  ValueDisplayed: 22  [0201]  (hidden comment: ERJ-1GNJ220C)
R27  ValueDisplayed: 22  [0201]  (hidden comment: ERJ-1GNJ220C)
R28  ValueDisplayed: 22  [0201]  (hidden comment: ERJ-1GNJ220C)
R29  ValueDisplayed: 22  [0201]  (hidden comment: ERJ-1GNJ220C)
R30  ValueDisplayed: 22  [0201]  (hidden comment: ERJ-1GNJ220C)
R31  ValueDisplayed: 22  [0201]  (hidden comment: ERJ-1GNJ220C)
R32  ValueDisplayed: 22  [0201]  (hidden comment: ERJ-1GNJ220C)
R33  value 0  [0402L]  (hidden comment: ERJ-2GE0R00X)
R34  ValueDisplayed: 22  [0201]  (hidden comment: ERJ-1GNJ220C)
R35  ValueDisplayed: 22  [0201]  (hidden comment: ERJ-1GNJ220C)
R36  value 0  [0402L]  (hidden comment: ERJ-2GE0R00X)
R37  ValueDisplayed: 22  [0201]  (hidden comment: ERJ-1GNJ220C)
R38  ValueDisplayed: 22  [0201]  (hidden comment: ERJ-1GNJ220C)
R39  value 0  [0402L]  (hidden comment: ERJ-2GE0R00X)
R40  ValueDisplayed: 22  [0201]  (hidden comment: ERJ-1GNJ220C)
R41  ValueDisplayed: 2.2k  [0402]  (hidden comment: CRCW04022K20JNED)
R42  ValueDisplayed: 22  [0201]  (hidden comment: ERJ-1GNJ220C)
R43  ValueDisplayed: 0.005  [0603]  (hidden comment: ERJ3LWFR005V)
R44  ValueDisplayed: 100  [0201]  (hidden comment: RC0201FR-7D100RL)
R45  ValueDisplayed: 100  [0201]  (hidden comment: RC0201FR-7D100RL)
R46  value 0  [0402L]  (hidden comment: ERJ-2GE0R00X)
R47  ValueDisplayed: 120k  [0603]  (hidden comment: RG1608P-124-B-T5)
R48  ValueDisplayed: 100  [0201]  (hidden comment: RC0201FR-7D100RL)
R49  ValueDisplayed: 100  [0201]  (hidden comment: RC0201FR-7D100RL)
R50  ValueDisplayed: 100  [0201]  (hidden comment: RC0201FR-7D100RL)
R51  ValueDisplayed: 100  [0201]  (hidden comment: RC0201FR-7D100RL)
R52  ValueDisplayed: 100  [0201]  (hidden comment: RC0201FR-7D100RL)
R53  ValueDisplayed: 100  [0201]  (hidden comment: RC0201FR-7D100RL)
R54  ValueDisplayed: 100  [0201]  (hidden comment: RC0201FR-7D100RL)
R55  ValueDisplayed: 100  [0201]  (hidden comment: RC0201FR-7D100RL)
R56  ValueDisplayed: 100  [0201]  (hidden comment: RC0201FR-7D100RL)
R57  ValueDisplayed: 100  [0201]  (hidden comment: RC0201FR-7D100RL)
R58  ValueDisplayed: 100  [0201]  (hidden comment: RC0201FR-7D100RL)
R59  ValueDisplayed: 100  [0201]  (hidden comment: RC0201FR-7D100RL)
R60  ValueDisplayed: 100  [0201]  (hidden comment: RC0201FR-7D100RL)
R61  ValueDisplayed: 100  [0201]  (hidden comment: RC0201FR-7D100RL)
R62  ValueDisplayed: 100  [0201]  (hidden comment: RC0201FR-7D100RL)
R63  ValueDisplayed: 100  [0201]  (hidden comment: RC0201FR-7D100RL)
R64  ValueDisplayed: 100  [0201]  (hidden comment: RC0201FR-7D100RL)
R65  ValueDisplayed: 100  [0201]  (hidden comment: RC0201FR-7D100RL)
R77  ValueDisplayed: 100  [0201]  (hidden comment: RC0201FR-7D100RL)
R126  ValueDisplayed: 100k  [0201]  (hidden comment: RC0201FR-07100KL)
R128  ValueDisplayed: 100k  [0201]  (hidden comment: RC0201FR-07100KL)
R218  ValueDisplayed: 100k  [0201]  (hidden comment: RC0201FR-07100KL)
R219  ValueDisplayed: 100k  [0201]  (hidden comment: RC0201FR-07100KL)
R222  value 0  [0402L]  (hidden comment: ERJ-2GE0R00X)
SW1  434351045816  [FP-434351045816_SMT_SW_4MM7_4MM5-MFG]  (value not drawn)
TP12  TESTPOINT  [TP_25MIL-SMT]  (value not drawn)  (no BOM)
U4  TMS320F28P650DK9NMRR  [NMR0169A-MFG]  (parts A,B,C of 4)
U5  REF6230IDGKR  [DGK0008A_N]

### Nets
3V3: C43.1 J1.6 R20.2 R21.1 R22.1 R23.1 R33.2 R41.2 R126.1 U5.1(VIN) U5.2(EN)
GND: C42.2 C43.2 C44.2 C45.2 C46.2 C47.2 C48.2 C49.2 C50.2 C51.2 C52.2 C53.2 C54.2 C55.2 C56.2 C57.2 C58.2 C59.2 C60.2 C61.2 C62.2 C63.2 C64.2 C65.2 C66.2 C67.2 C68.2 C94.2 J1.1 R36.1 R47.1 R128.1 R218.1 R219.1 SW1.2 SW1.4 U4.J1(VREFLOC) U4.K1(VREFLOA) U4.N4(VREFLOB) U5.7(GND_F) U5.8(GND_S)
ADC_VREF: R43.2 R46.2 U5.5(OUT_S) U5.6(OUT_F)
BOOTPIN1: U4.A11(GPIO72)
CAN_TX: R42.2 ; off-sheet CAN_TX
CANA_RX: U4.N11(GPIO36)
CANA_TX: R42.1 U4.M11(GPIO37)
Current_A1: C50.1 R48.2 U4.L3(A0/DACA_OUT)
Current_A2: C51.1 R51.2 U4.K3(A1)
Current_A3: C52.1 R54.2 U4.J3(A2)
Current_A4: C53.1 R57.2 U4.H3(A3)
Current_A5: C54.1 R60.2 U4.H2(A4)
Current_A6: C55.1 R63.2 U4.H1(A5)
Current_B1: C56.1 R49.2 U4.N2(B0/VDAC)
Current_B2: C57.1 R52.2 U4.J4(B6/GPIO207)
Current_B3: C58.1 R55.2 U4.M3(B2)
Current_B4: C59.1 R58.2 U4.L4(B3)
Current_B5: C60.1 R61.2 U4.M6(B4/GPIO215)
Current_B6: C61.1 R64.2 U4.N6(B5/GPIO216)
Current_C1: C62.1 R50.2 U4.F1(C0/GPIO199)
Current_C2: C63.1 R53.2 U4.G1(C1/GPIO200)
Current_C3: C64.1 R56.2 U4.H4(C2)
Current_C4: C65.1 R59.2 U4.H5(C3/GPIO206)
Current_C5: C66.1 R62.2 U4.H6(C4/GPIO205)
Current_C6: C67.1 R65.2 U4.G6(C5/GPIO204)
DAC_OUT: R77.2 TP12.1
DACC_OUT: C94.1 R77.1 U4.N3(B1/DACC_OUT)
DRV_FLT_AX1: U4.G12(GPIO64)
DRV_FLT_AX2: U4.G11(GPIO65)
DRV_FLT_AX3: U4.G10(GPIO66)
DRV_FLT_AX4: U4.B13(GPIO68)
DRV_FLT_AX5: U4.B11(GPIO71)
DRV_FLT_AX6: U4.G2(C9/GPIO201)
DRV_nSleep: U4.C10(GPIO73)
DRV_OFF: J14.2
DRV_OFF_MCU: J14.3 U4.B10(GPIO74)
DRV_OFF_PMIC: J14.1
ENC_SPI_CS1: U4.A10(GPIO75)
ENC_SPI_CS2: U4.F11(GPIO45)
ENC_SPI_CS3: U4.F10(GPIO44)
ENC_SPI_CS4: U4.C12(GPIO42)
ENC_SPI_CS5: U4.M12(GPIO41)
ENC_SPI_CS6: U4.F12(GPIO32)
ESC_I2C_SCL: U4.L9(GPIO30)
ESC_I2C_SDA: U4.N12(GPIO40)
ESC_LED_ERR: U4.L5(A10/GPIO213)
ESC_LED_RUN: U4.H11(GPIO61)
ESC_MDC: R32.1 U4.H10(GPIO62)
ESC_MDIO: R19.1 U4.K12(GPIO53)
ESC_PHY0_LINK: U4.J13(GPIO55)
ESC_PHY_RST: U4.E9(GPIO76)
ESC_RX0_CLK: U4.D9(GPIO77)
ESC_RX0_D0: U4.E8(GPIO80)
ESC_RX0_D1: U4.K8(GPIO28)
ESC_RX0_D2: U4.D8(GPIO82)
ESC_RX0_D3: U4.C8(GPIO83)
ESC_RX0_DV: U4.C9(GPIO78)
ESC_RX0_ERR: U4.B9(GPIO79)
ESC_TX0_CLK: U4.A7(GPIO85)
ESC_TX0_D0: U4.C7(GPIO87)
ESC_TX0_D1: U4.C5(GPIO88)
ESC_TX0_D2: U4.D5(GPIO89)
ESC_TX0_D3: U4.E5(GPIO90)
ESC_TX0_EN: U4.A8(GPIO84)
Fault_IN: R222.2 ; off-sheet Fault_IN
FSIRXA_CLK: U4.K13(GPIO54)
FSIRXA_D0: U4.D10(GPIO103)
FSITXA_CLK: R18.1 U4.K10(GPIO51)
FSITXA_CLK_P1: R18.2 ; off-sheet FSITXA_CLK_P1
FSITXA_D0: R17.1 U4.L13(GPIO49)
FSITXA_D0_P1: R17.2 ; off-sheet FSITXA_D0_P1
I2CA_SCL: U4.H12(GPIO105)
I2CA_SDA: U4.A9(GPIO104)
I_A1: R48.1 ; off-sheet I_A1
I_A2: R51.1 ; off-sheet I_A2
I_A3: R54.1 ; off-sheet I_A3
I_A4: R57.1 ; off-sheet I_A4
I_A5: R60.1 ; off-sheet I_A5
I_A6: R63.1 ; off-sheet I_A6
I_B1: R49.1 ; off-sheet I_B1
I_B2: R52.1 ; off-sheet I_B2
I_B3: R55.1 ; off-sheet I_B3
I_B4: R58.1 ; off-sheet I_B4
I_B5: R61.1 ; off-sheet I_B5
I_B6: R64.1 ; off-sheet I_B6
I_C1: R50.1 ; off-sheet I_C1
I_C2: R53.1 ; off-sheet I_C2
I_C3: R56.1 ; off-sheet I_C3
I_C4: R59.1 ; off-sheet I_C4
I_C5: R62.1 ; off-sheet I_C5
I_C6: R65.1 ; off-sheet I_C6
MCU_CLK_25M: U4.D13(GPIO220/X1) ; off-sheet MCU_CLK_25M
MDC: R32.2 ; off-sheet MDC
MDIO: R19.2 ; off-sheet MDIO
PMIC_NRST: R39.1 ; off-sheet PMIC_NRST
PWM_A1_H: U4.E7(GPIO0)
PWM_A1_L: U4.A6(GPIO1)
PWM_A2_H: U4.A5(GPIO6)
PWM_A2_L: U4.B5(GPIO7)
PWM_A3_H: U4.B1(GPIO12)
PWM_A3_L: U4.C1(GPIO13)
PWM_A4_H: U4.D3(GPIO18)
PWM_A4_L: U4.D1(GPIO19)
PWM_A5_H: U4.D7(GPIO24)
PWM_A5_L: U4.B8(GPIO25)
PWM_A6_H: U4.B4(GPIO91)
PWM_A6_L: U4.A4(GPIO92)
PWM_B1_H: U4.B6(GPIO2)
PWM_B1_L: U4.C6(GPIO3)
PWM_B2_H: U4.E3(GPIO8)
PWM_B2_L: U4.F3(GPIO9)
PWM_B3_H: U4.C2(GPIO14)
PWM_B3_L: U4.C3(GPIO15)
PWM_B4_H: U4.E1(GPIO20)
PWM_B4_L: U4.E2(GPIO21)
PWM_B5_H: U4.L10(GPIO26)
PWM_B5_L: U4.D11(GPIO27)
PWM_B6_H: U4.A3(GPIO93)
PWM_B6_L: U4.A2(GPIO94)
PWM_C1_H: U4.D6(GPIO4)
PWM_C1_L: U4.E6(GPIO5)
PWM_C2_H: U4.B3(GPIO10)
PWM_C2_L: U4.B2(GPIO11)
PWM_C3_H: U4.C4(GPIO16)
PWM_C3_L: U4.D4(GPIO17)
PWM_C4_H: U4.D2(GPIO22)
PWM_C4_L: U4.F2(GPIO23)
PWM_C5_H: U4.K9(GPIO50)
PWM_C5_L: U4.L8(GPIO29)
PWM_C6_H: U4.K7(GPIO34)
PWM_C6_L: U4.N8(GPIO35)
SPIA_CLK_AX1_2: R29.2 ; off-sheet SPIA_CLK_AX1_2
SPIA_CLK_AX12: R29.1 U4.J12(GPIO56)
SPIA_PICO_AX1_2: R27.2 ; off-sheet SPIA_PICO_AX1_2
SPIA_PICO_AX12: R27.1 U4.G4(C7/GPIO198)
SPIA_POCI_AX12: R219.2 U4.L7(GPIO33)
SPIB_CLK_AX3_4: R35.2 ; off-sheet SPIB_CLK_AX3_4
SPIB_CLK_AX34: R35.1 U4.G5(C6/GPIO203)
SPIB_PICO_AX3_4: R34.2 ; off-sheet SPIB_PICO_AX3_4
SPIB_PICO_AX34: R34.1 U4.K4(B7/GPIO208)
SPIB_POCI_AX34: R218.2 U4.G3(C8/GPIO202)
SPIC_CLK_AX5_6: R38.2 ; off-sheet SPIC_CLK_AX5_6
SPIC_CLK_AX56: R38.1 U4.K11(GPIO52)
SPIC_PICO_AX5_6: R37.2 ; off-sheet SPIC_PICO_AX5_6
SPIC_PICO_AX56: R37.1 U4.B12(GPIO69)
SPIC_POCI_AX56: R128.2 U4.A12(GPIO70)
SPID_CLK_DRV: R30.1 U4.N7(B9/GPIO218)
SPID_CLK_DRVCFG: R30.2 ; off-sheet SPID_CLK_DRVCFG
SPID_CS1_DRV: U4.F13(GPIO133)
SPID_CS2_DRV: U4.M13(GPIO48)
SPID_CS3_DRV: U4.J11(GPIO57)
SPID_CS4_DRV: U4.J10(GPIO58)
SPID_CS5_DRV: U4.H13(GPIO59)
SPID_CS6_DRV: U4.G13(GPIO63)
SPID_PICO_DRV: R31.1 U4.L6(A11/GPIO214)
SPID_PICO_DRVCFG: R31.2 ; off-sheet SPID_PICO_DRVCFG
SPID_POCI_DRV: R126.2 U4.M7(B8/GPIO217)
TCK: J1.4 R22.2 R24.1
TDI: J1.3 R21.2 R25.1
TDO: J1.5 R23.2 R26.1
Temp_PCB: R45.1 ; off-sheet Temp_PCB
TEMP_SEN: C47.1 R45.2 U4.K5(A7/GPIO210)
TMS: J1.2 R20.1 R28.1
UART_TX: R40.2 ; off-sheet UART_TX
UARTA_RX: U4.C11(GPIO43)
UARTA_TX: R40.1 U4.L11(GPIO38)
VBUS_SEN: C46.1 R44.2 U4.J5(A6/GPIO209)
VBUS_SENSE: R44.1 ; off-sheet VBUS_SENSE
VREGENZ: R33.1 R36.2 U4.E10(VREGENZ)
XRSn: C42.1 R39.2 R41.1 SW1.1 SW1.3 U4.D12(~{XRS})
NetC44_1: C44.1 C49.1 C68.1 R46.1 U4.J2(VREFHIC) U4.K2(VREFHIA) U4.M4(VREFHIB)
NetC45_1: C45.1 R43.1
NetC48_1: C48.1 U5.4(FILT)
NetR24_2: R24.2 U4.M10(TCK)
NetR25_2: R25.2 U4.N9(GPIO222/TDI)
NetR26_2: R26.2 U4.M9(GPIO223/TDO)
NetR28_2: R28.2 U4.N10(TMS)
NetR47_2: R47.2 U5.3(SS)
NetR222_1: R222.1 U4.L12(GPIO224/ERRORSTS)

Not connected (* = marked no-connect by the designer): U4 B7(GPIO86)* E4(GPIO99)* E13(GPIO221/X2)* J6(A8/GPIO211)* K6(A9/GPIO212)* M1(A14/B14/C14)* M2(A15/B15/C15)*

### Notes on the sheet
- EPWM1A
- EPWM1B
- FSITXA_CLK
- EPWM15A
- JTAG - Debug
- EPWM4A
- EPWM2A
- EPWM2B
- EPWM3A
- EPWM3B
- FSIRXA_CLK
- ESC_MDIO_DATA
- ESC_PHY0_LINKSTATUS
- ENC_AX56_SPIC_CLK
- ENC_AX12_SPIA_CLK
- EPWM5A
- EPWM5B
- EPWM4B
- EPWM6A
- EPWM6B
- ESC_LED_RUN
- ESC_MDIO_CLK
- SPID_CS3_DRVCFG
- SPID_CS5_DRVCFG
- SPID_CS4_DRVCFG
- EPWM7A
- EPWM7B
- EPWM8A
- EPWM8B
- EPWM9A
- SPID_CS6_DRVCFG
- DRV_FLT_AX1
- DRV_FLT_AX2
- DRV_FLT_AX3
- DRV_FLT_AX4
- Reset
- EPWM9B
- EPWM10A
- EPWM10B
- EPWM11A
- EPWM11B
- ENC_AX56_SPIC_PICO
- ENC_AX56_SPIC_POCI
- DRV_FLT_AX5
- DRV_nSLEEP_ALL_AXIS
- BOOT PIN1
- EPWM12A
- EPWM12B
- EPWM13A
- EPWM13B
- EPWM14A
- ESC_PHY_RESETn
- ESC_RX0_CLK
- ESC_RX0_DV
- ENC_SPI_CS1
- DRV_OFF_ALL_AXIS
- PMIC_NRST and RST push-buttons must be high to de-assert XRSn.
- ESC_RX0_DATA1
- EPWM14B
- EPWM15B
- ENC_SPI_CS6
- ESC_I2C_SCL
- ESC_RX0_DATA0
- ESC_RX0_DATA2
- ESC_RX0_DATA3
- ESC_RX0_ERR
- ESC_TX0_EN
- BOOT PIN2
- ENC_AX12_SPIA_POCI
- CANA_RX
- CANA_TX
- EPWM18A
- EPWM18B
- ESC_TX0_CLK
- ESC_TX0_DATA0
- ESC_TX0_DATA1
- ESC_TX0_DATA2
- UARTA_RX
- UARTA_TX
- ENC_SPI_CS4
- ENC_SPI_CS5
- ESC_I2C_SDA
- ESC_TX0_DATA3
- EPWM16A
- EPWM16B
- EPWM17A
- EPWM17B
- FSITXA_D0
- ENC_SPI_CS2
- SPID_CS2_DRVCFG
- ENC_SPI_CS3
- I2CA_SCL
- FSIRXA_D0
- SPID_CS1_DRVCFG
- I2CA_SDA
- ADC REF
- (near U4) F28P65x Pin_IO
- ADC
- ESC_LED_ERR
- SPID_PICO_DRVCFG
- ENC_AX34_SPIB_PICO
- SPID_CLK_DRVCFG
- SPID_POCI_DRVCFG
- ENC_AX12_SPIA_PICO
- ENC_AX34_SPIB_CLK
- ENC_AX34_SPIB_POCI
- Place near U1
- DRV_FLT_AX6

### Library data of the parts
C42 C43 = CMP-0006228-2: CAP, CERM, 0.1 uF, 16 V, +/- 10%, X7R, 0402; Manufacturer: Wurth Elektronik; TaMin_C: -55°C; Polarized: N; SizeAreaWB_mm2: 3; Value1: Unknown; U/M: EA; Value: 0.1uF; TaMax_C: 125°C; SizeZ_mm: 0.6; SizeX_mm: 1; SizeY_mm: 0.5; Value2: 16V; Cap_F: 100nF; AEC Category: Q200
C44 C48 C49 C68 = CMP-0007341-4: CAP, CERM, 4.7 uF, 16 V, +/- 10%, X5R, 0603; Manufacturer: MuRata; TaMin_C: -55°C; Polarized: N; SizeAreaWB_mm2: 4.68; Value1: Unknown; U/M: EA; Value: 4.7uF; TaMax_C: 85°C; SizeZ_mm: 1; SizeX_mm: 1.6; SizeY_mm: 0.8; Value2: 16V; SizeArea_mm2: 1.28; Cap_F: 4.7µF; AEC Category: Q200
C45 = CMP-0007324-5: CAP, CERM, 22 uF, 10 V, +/- 20%, X5R, 0603; Manufacturer: MuRata; TaMin_C: -55°C; Polarized: N; SizeAreaWB_mm2: 4.68; Value1: Unknown; U/M: EA; Value: 22uF; TaMax_C: 85°C; SizeZ_mm: 1; SizeX_mm: 1.6; SizeY_mm: 0.8; Value2: 10V; SizeArea_mm2: 1.28; Cap_F: 22µF; AEC Category: Q200
C46 C47 C50-C67 C94 = CMP-0009776-1: CAP, CERM, 680 pF, 25 V, +/- 10%, X7R, 0201; Manufacturer: MuRata; TaMin_C: -55°C; Polarized: N; SizeAreaWB_mm2: 2.08; Value1: Unknown; U/M: EA; Value: 680pF; TaMax_C: 125°C; SizeZ_mm: 0.26; SizeX_mm: 0.6; SizeY_mm: 0.3; SizeArea_mm2: 0.18; AEC Category: Q200
J1 = CMP-0054561-1: Header, 50mil, 6x1, Gold,  TH; Manufacturer: Sullins Connector Solutions; CT: FALSE; CNHeader: TRUE
J14 = CMP-0054564-1: Header, 50mil, 3x1, Gold, TH; Manufacturer: Sullins Connector Solutions; CNHeader: TRUE; Green_Lifecycle: Not Set; Shrouded: N; Gender: Male; Green_REACh: Incomplete; Row_Count: 1; CT: FALSE
R17-R19 R24-R32 R34 R35 R37 R38 R40 R42 = CMP-0027015-3: RES, 22, 5%, 0.05 W, AEC-Q200 Grade 1, 0201; Manufacturer: Panasonic; Power_W: 50mW; TempCo: 200 ppm/C; Value_Code: 22R0; U/M: EA; Value: 22; EIA_Code: E24; SizeX_mm: 0.6; SizeY_mm: 0.3; SizeZ_mm: 0.26; Value2: 0.05W; SizeArea_mm2: 0.18; AEC Qualified: Y; AEC Grade: 1; AEC Category: Q200
R20 = CMP-0026231-2: RES, 2.20 k, 1%, 0.063 W, AEC-Q200 Grade 0, 0402; Manufacturer: Vishay-Dale; Power_W: 63mW; TempCo: 100 ppm/C; Value_Code: 2k20; Value: 2.20k; Res_ohm: 2.2k; SizeX_mm: 1; SizeY_mm: 0.5; SizeZ_mm: 0.6; Value2: 0.063W; AEC Qualified: Y; AEC Category: Q200; AEC Grade: 0
R21-R23 = CMP-0026658-1: RES, 10.0 k, 1%, 0.1 W, 0402; Manufacturer: Panasonic; Power_W: 100mW; TempCo: 100 ppm/C; Value_Code: 10k0; U/M: EA; Value: 10.0k; EIA_Code: E96; Res_ohm: 10k; SizeX_mm: 1; SizeY_mm: 0.5; SizeZ_mm: 0.6; Value2: 0.1W; VDC_V: 50V; AEC Category: Q200
R33 R36 R39 R46 R222 = CMP-0026992-3: RES, 0, 5%, 0.1 W, AEC-Q200 Grade 0, 0402; Manufacturer: Panasonic; Power_W: 100mW; TempCo: 600 ppm/C; Value_Code: 0000; EIA_Code: E24; SizeX_mm: 1; SizeY_mm: 0.5; SizeZ_mm: 0.6; Value2: 0.1W; AEC Qualified: Y; VDC_V: 50V; AEC Category: Q200; SizeAreaWB_mm2: 3
R41 = CMP-0026890-5: as R7 on sheet TIDA-010992_02_Power
R43 = CMP-0022710-2: RES, 0.005, 1%, 0.25 W, AEC-Q200 Grade 1, 0603; Manufacturer: Panasonic; Power_W: 250mW; TempCo: ppm/C; Value_Code: 5L000; U/M: EA; Value: 0.005; EIA_Code: E96; Res_ohm: 5m; SizeX_mm: 1.6; SizeY_mm: 0.8; SizeZ_mm: 1; Value2: 0.25W; SizeArea_mm2: 1.28; AEC Qualified: Y; AEC Category: Q200
R44 R45 R48-R65 R77 = CMP-0027944-1: RES, 100, 1%, 0.05 W, 0201; Manufacturer: Yageo America; Power_W: 50mW; TempCo: 200 ppm/C; Value_Code: 100R; U/M: EA; Value: 100; EIA_Code: E96; SizeX_mm: 0.6; SizeY_mm: 0.3; SizeZ_mm: 0.26; Value2: 0.05W; SizeArea_mm2: 0.18; AEC Qualified: N; VDC_V: 25V; AEC Category: Q200
R47 = CMP-0023427-3: RES, 120 k, 0.1%, 0.1 W, 0603; Manufacturer: Susumu Co Ltd; Power_W: 100mW; TempCo: 25 ppm/C; U/M: EA; Value: 120k; EIA_Code: E192; SizeX_mm: 1.6; SizeY_mm: 0.8; SizeZ_mm: 1; Value2: 0.1W; SizeArea_mm2: 1.28; VDC_V: 75V; AEC Category: Q200
R126 R128 R218 R219 = CMP-0027293-2: RES, 100 k, 1%, 0.05 W, 0201; Manufacturer: Yageo America; Power_W: 50mW; TempCo: 200 ppm/C; U/M: EA; Value: 100k; EIA_Code: E96; SizeX_mm: 0.6; SizeY_mm: 0.3; SizeZ_mm: 0.26; Value2: 0.05W; SizeArea_mm2: 0.18; AEC Qualified: N; VDC_V: 25V; AEC Category: Q200
SW1 = CMP-0093456-1: Tactile Switch SPST-NO Side Actuated Surface Mount, Right Angle; Manufacturer: Wurth Electronics; Operating Force: 160gf; SizeZ_mm: 1.75mm; AEC Qualified: No; Electromechanical Life: 200000Cycles; VDC_V: 12V; Contact Current Rating: 50mA; Coil Resistance_ohm: 100mΩ
TP12 = CMP-0078143-3: TEST POINT.  No entry in BOM.
U4 = CMP-0098413-1: Real-Time Microcontroller, NFBGA169; Manufacturer: Texas Instruments; SizeZ_mm: 1mm; AEC Qualified: No; Core Architecture: C28x; Data Bus Width: 32bits; Frequency_Fixed: 200MHz; Interface: I2C,SPI,UART,CAN,USB,LIN,SCI,Ethernet; Max Supply Voltage: 3.63V; Memory Size: 1.28MBytes; Memory Type: FLASH; Min Supply Voltage: 1.14V; Number Of A/D Converters: 3; Number Of Adc Channels: 34; Number Of Cores: 2; Number Of Ethernet Channels: 1; Number Of I/Os: 119; Number Of Pwm Channels: 36; Number Of Spi Channels: 4; Number Of Timers/Counters: 6; Ram Size: 248KBytes; Standoff Height: 0.19mm; TaMax_C: +125°C; TaMin_C: -40°C; TJmax_C: +155°C
U5 = CMP-0077709-1: High-Precision Voltage Reference with Integrated High-Bandwidth Buffer, DGK0008A (VSSOP-8); Alternate PartNumber: REF6230IDGKT; Alternate Manufacturer: Texas Instruments; SizeAreaWB_mm2: 35.955; SizeZ_mm: 1.1; SizeX_mm: 5.05; SizeY_mm: 3.1; SizeArea_mm2: 15.655; CompType: IC; AEC Qualified: N; AEC Category: Q200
